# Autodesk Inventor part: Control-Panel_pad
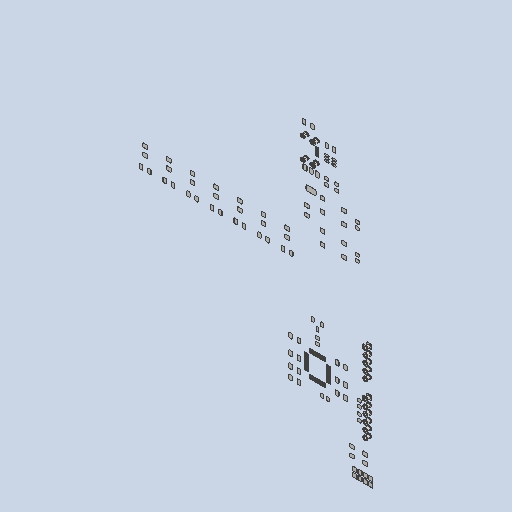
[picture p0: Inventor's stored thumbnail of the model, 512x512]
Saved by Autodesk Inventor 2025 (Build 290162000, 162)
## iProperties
Created: 2026-09
Part Number: Control-Panel_pad
Material: Generic
Document SubType Name: Modeling
Designer: Leonardo
Density: 1 g/cm^3
Appearance: Default
Author: Leonardo
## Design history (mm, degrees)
feature "Base1"
feature "Base2"
feature "Base3"
feature "Base4"
feature "Base5"
feature "Base6"
feature "Base7"
feature "Base8"
feature "Base9"
feature "Base10"
feature "Base11"
feature "Base12"
feature "Base13"
feature "Base14"
feature "Base15"
feature "Base16"
feature "Base17"
feature "Base18"
feature "Base19"
feature "Base20"
feature "Base21"
feature "Base22"
feature "Base23"
feature "Base24"
feature "Base25"
feature "Base26"
feature "Base27"
feature "Base28"
feature "Base29"
feature "Base30"
feature "Base31"
feature "Base32"
feature "Base33"
feature "Base34"
feature "Base35"
feature "Base36"
feature "Base37"
feature "Base38"
feature "Base39"
feature "Base40"
feature "Base41"
feature "Base42"
feature "Base43"
feature "Base44"
feature "Base45"
feature "Base46"
feature "Base47"
feature "Base48"
feature "Base49"
feature "Base50"
feature "Base51"
feature "Base52"
feature "Base53"
feature "Base54"
feature "Base55"
feature "Base56"
feature "Base57"
feature "Base58"
feature "Base59"
feature "Base60"
feature "Base61"
feature "Base62"
feature "Base63"
feature "Base64"
feature "Base65"
feature "Base66"
feature "Base67"
feature "Base68"
feature "Base69"
feature "Base70"
feature "Base71"
feature "Base72"
feature "Base73"
feature "Base74"
feature "Base75"
feature "Base76"
feature "Base77"
feature "Base78"
feature "Base79"
feature "Base80"
feature "Base81"
feature "Base82"
feature "Base83"
feature "Base84"
feature "Base85"
feature "Base86"
feature "Base87"
feature "Base88"
feature "Base89"
feature "Base90"
feature "Base91"
feature "Base92"
feature "Base93"
feature "Base94"
feature "Base95"
feature "Base96"
feature "Base97"
feature "Base98"
feature "Base99"
feature "Base100"
feature "Base101"
feature "Base102"
feature "Base103"
feature "Base104"
feature "Base105"
feature "Base106"
feature "Base107"
feature "Base108"
feature "Base109"
feature "Base110"
feature "Base111"
feature "Base112"
feature "Base113"
feature "Base114"
feature "Base115"
feature "Base116"
feature "Base117"
feature "Base118"
feature "Base119"
feature "Base120"
feature "Base121"
feature "Base122"
feature "Base123"
feature "Base124"
feature "Base125"
feature "Base126"
feature "Base127"
feature "Base128"
feature "Base129"
feature "Base130"
feature "Base131"
feature "Base132"
feature "Base133"
feature "Base134"
feature "Base135"
feature "Base136"
feature "Base137"
feature "Base138"
feature "Base139"
feature "Base140"
feature "Base141"
feature "Base142"
feature "Base143"
feature "Base144"
feature "Base145"
feature "Base146"
feature "Base147"
feature "Base148"
feature "Base149"
feature "Base150"
feature "Base151"
feature "Base152"
feature "Base153"
feature "Base154"
feature "Base155"
feature "Base156"
feature "Base157"
feature "Base158"
feature "Base159"
feature "Base160"
feature "Base161"
feature "Base162"
feature "Base163"
feature "Base164"
feature "Base165"
feature "Base166"
feature "Base167"
feature "Base168"
feature "Base169"
feature "Base170"
feature "Base171"
feature "Base172"
feature "Base173"
feature "Base174"
feature "Base175"
feature "Base176"
feature "Base177"
feature "Base178"
feature "Base179"
feature "Base180"
feature "Base181"
feature "Base182"
feature "Base183"
feature "Base184"
feature "Base185"
feature "Base186"
feature "Base187"
feature "Base188"
feature "Base189"
feature "Base190"
feature "Base191"
feature "Base192"
feature "Base193"
feature "Base194"
feature "Base195"
feature "Base196"
feature "Base197"
feature "Base198"
feature "Base199"
feature "Base200"
feature "Base201"
feature "Base202"
feature "Base203"
feature "Base204"
feature "Base205"
feature "Base206"
feature "Base207"
feature "Base208"
feature "Base209"
feature "Base210"
feature "Base211"
feature "Base212"
feature "Base213"
feature "Base214"
feature "Base215"
feature "Base216"
feature "Base217"
feature "Base218"
feature "Base219"
feature "Base220"
feature "Base221"
feature "Base222"
feature "Base223"
feature "Base224"
feature "Base225"
body "Solid1"
body "Solid2"
body "Solid3"
body "Solid4"
body "Solid5"
body "Solid6"
body "Solid7"
body "Solid8"
body "Solid9"
body "Solid10"
body "Solid11"
body "Solid12"
body "Solid13"
body "Solid14"
body "Solid15"
body "Solid16"
body "Solid17"
body "Solid18"
body "Solid19"
body "Solid20"
body "Solid21"
body "Solid22"
body "Solid23"
body "Solid24"
body "Solid25"
body "Solid26"
body "Solid27"
body "Solid28"
body "Solid29"
body "Solid30"
body "Solid31"
body "Solid32"
body "Solid33"
body "Solid34"
body "Solid35"
body "Solid36"
body "Solid37"
body "Solid38"
body "Solid39"
body "Solid40"
body "Solid41"
body "Solid42"
body "Solid43"
body "Solid44"
body "Solid45"
body "Solid46"
body "Solid47"
body "Solid48"
body "Solid49"
body "Solid50"
body "Solid51"
body "Solid52"
body "Solid53"
body "Solid54"
body "Solid55"
body "Solid56"
body "Solid57"
body "Solid58"
body "Solid59"
body "Solid60"
body "Solid61"
body "Solid62"
body "Solid63"
body "Solid64"
body "Solid65"
body "Solid66"
body "Solid67"
body "Solid68"
body "Solid69"
body "Solid70"
body "Solid71"
body "Solid72"
body "Solid73"
body "Solid74"
body "Solid75"
body "Solid76"
body "Solid77"
body "Solid78"
body "Solid79"
body "Solid80"
body "Solid81"
body "Solid82"
body "Solid83"
body "Solid84"
body "Solid85"
body "Solid86"
body "Solid87"
body "Solid88"
body "Solid89"
body "Solid90"
body "Solid91"
body "Solid92"
body "Solid93"
body "Solid94"
body "Solid95"
body "Solid96"
body "Solid97"
body "Solid98"
body "Solid99"
body "Solid100"
body "Solid101"
body "Solid102"
body "Solid103"
body "Solid104"
body "Solid105"
body "Solid106"
body "Solid107"
body "Solid108"
body "Solid109"
body "Solid110"
body "Solid111"
body "Solid112"
body "Solid113"
body "Solid114"
body "Solid115"
body "Solid116"
body "Solid117"
body "Solid118"
body "Solid119"
body "Solid120"
body "Solid121"
body "Solid122"
body "Solid123"
body "Solid124"
body "Solid125"
body "Solid126"
body "Solid127"
body "Solid128"
body "Solid129"
body "Solid130"
body "Solid131"
body "Solid132"
body "Solid133"
body "Solid134"
body "Solid135"
body "Solid136"
body "Solid137"
body "Solid138"
body "Solid139"
body "Solid140"
body "Solid141"
body "Solid142"
body "Solid143"
body "Solid144"
body "Solid145"
body "Solid146"
body "Solid147"
body "Solid148"
body "Solid149"
body "Solid150"
body "Solid151"
body "Solid152"
body "Solid153"
body "Solid154"
body "Solid155"
body "Solid156"
body "Solid157"
body "Solid158"
body "Solid159"
body "Solid160"
body "Solid161"
body "Solid162"
body "Solid163"
body "Solid164"
body "Solid165"
body "Solid166"
body "Solid167"
body "Solid168"
body "Solid169"
body "Solid170"
body "Solid171"
body "Solid172"
body "Solid173"
body "Solid174"
body "Solid175"
body "Solid176"
body "Solid177"
body "Solid178"
body "Solid179"
body "Solid180"
body "Solid181"
body "Solid182"
body "Solid183"
body "Solid184"
body "Solid185"
body "Solid186"
body "Solid187"
body "Solid188"
body "Solid189"
body "Solid190"
body "Solid191"
body "Solid192"
body "Solid193"
body "Solid194"
body "Solid195"
body "Solid196"
body "Solid197"
body "Solid198"
body "Solid199"
body "Solid200"
body "Solid201"
body "Solid202"
body "Solid203"
body "Solid204"
body "Solid205"
body "Solid206"
body "Solid207"
body "Solid208"
body "Solid209"
body "Solid210"
body "Solid211"
body "Solid212"
body "Solid213"
body "Solid214"
body "Solid215"
body "Solid216"
body "Solid217"
body "Solid218"
body "Solid219"
body "Solid220"
body "Solid221"
body "Solid222"
body "Solid223"
body "Solid224"
body "Solid225"
